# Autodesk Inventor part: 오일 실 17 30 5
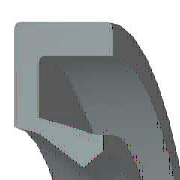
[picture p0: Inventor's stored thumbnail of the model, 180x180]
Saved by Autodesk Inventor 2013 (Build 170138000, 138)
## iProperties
Created: 2012-02
Part Number: 오일 실 17 30 5
Material: 고무
Description: 오일 실 - 스프링 장착, 비스프링, 고무 덮개 G
Document SubType Name: Modeling
Standard: JIS B 2402
Designer: mduedu
Standards Organization: JIS
Language: ko-KR
Size Designation: 17 30 5 A
Categories: <MemberInstance><Categories><Category DisplayName="샤프트 부품" InternalName="7f7aeb1f-a693-4053-b835-cee3144e0d98" Mnemonic="SHFT"><Category DisplayName="실링" Intern
Density: 0.93 g/cm^3
IsCustomPart: 1
Author: mduedu
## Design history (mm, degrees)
body "Solid1"
revolve "회전1" stored, may be unused: angle "d29" = 360 deg
chamfer "모따기1" distance "d30" = 0.25 (= 0.05 x b); stored, may be unused: second distance "d31" = 0.5 (= 0.1 x b), angle "d39" = 45 deg
chamfer "모따기2" distance "d32" = 0.5 (= 0.1 x b); stored, may be unused: second distance "d33" = 0.25 (= 0.05 x b), angle "d40" = 45 deg
fillet "모깎기1" dims "d34" = 0.25 (= 0.05 x b)
sketch "스케치2"
  geometry: L1 (9.58, -3.438)-(9.905, -5); L2 (9.147, -3.282)-(9.58, -3.438); L3 (8.5, -1.72)-(9.147, -3.282); L4 (9.682, -1.22)-(8.5, -1.72); L5 (10.811, -3.75)-(9.682, -1.22); L6 (12.111, -3.75)-(10.811, -3.75); L7 (13.556, -1.25)-(12.111, -3.75); L8 (13.556, 0)-(13.556, -1.25); L9 (15, 0)-(13.556, 0); L10 (15, -5)-(15, 0); L11 (9.905, -5)-(15, -5); L12 (0, -9.6)-(0, 1.6) reference; L13 (28, 0)-(14, 0) reference
  constraints: 22 end point, 3 horizontal, 2 vertical
  dimensions: "d2" = 5 distance of L10.start L9.start (= b); "d4" = 1.25 vertical distance of L5.start L1.end (= 0.25 x b); "d6" = 1.44444 distance of L9.start L8.start (= 0.111111 x dd - 0.111111 x Diam); "d8" = 1.25 distance of L8.start L7.start (= 0.25 x b); "d10" = 1.44444 horizontal distance of L7.start L6.start (= 0.111111 x dd - 0.111111 x Diam); "d12" = 1.21951 vertical distance of L9.start L4.start (= 0.243902 x b); "d14" = 1.18182 horizontal distance of L4.start L3.start (= 0.0909091 x dd - 0.0909091 x Diam); "d16" = 0.5 vertical distance of L4.start L3.start (= 0.1 x b); "d18" = 1.3 distance of L6.start L5.start (= 0.1 x dd - 0.1 x Diam); "d20" = 1.5625 vertical distance of L3.start L2.start (= 0.3125 x b); "d22" = 0.64677 horizontal distance of L3.start L2.start (= 0.0497512 x dd - 0.0497512 x Diam); "d24" = 0.325 horizontal distance of L1.start L1.end (= 0.025 x dd - 0.025 x Diam); "d26" = 1.5625 vertical distance of L1.start L1.end (= 0.3125 x b); "d28" = 0.43333 horizontal distance of L2.start L1.start (= 0.0333333 x dd - 0.0333333 x Diam); "d35" = 0 distance between parallel lines of L13 L9; "d36" = 15 distance between parallel lines of L12 L10 (= 0.5 x dd); "d37" = 8.5 distance from line of L12 L3.start (= 0.5 x Diam)
other parameters: "Diam" = 17 [user parameter; used in 8 equation terms], "b" = 5 [user parameter; used in 12 equation terms], "d1" = 8 (derived), "d3" = 2 (derived), "d5" = 2.22222 (derived), "d7" = 2 (derived), "d9" = 2.22222 (derived), "d11" = 1.95122 (derived), "d13" = 1.81818 (derived), "d15" = 0.8 (derived), "d17" = 2 (derived), "d19" = 2.5 (derived), "d21" = 0.99502 (derived), "d23" = 0.5 (derived), "d25" = 2.5 (derived), "d27" = 0.66667 (derived), "d38" = 0
